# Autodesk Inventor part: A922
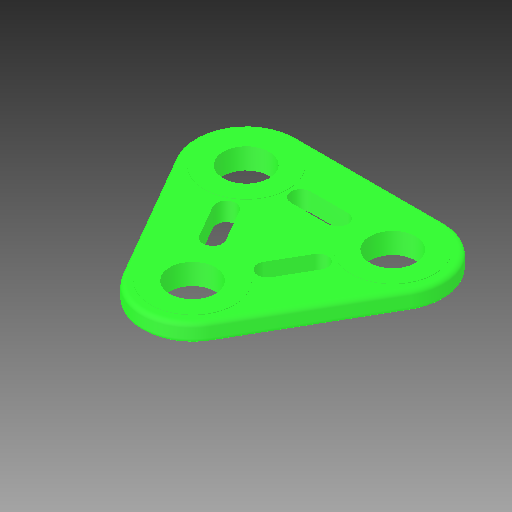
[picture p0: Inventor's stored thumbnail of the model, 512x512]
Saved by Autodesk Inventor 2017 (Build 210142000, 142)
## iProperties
Part Number: A922
Material: Générique
Document SubType Name: Modeling
Designer: ficho
Density: 1 g/cm^3
Appearance: Par défaut
Author: ficho
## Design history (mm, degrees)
feature "Solid1"
node "Solide1"
